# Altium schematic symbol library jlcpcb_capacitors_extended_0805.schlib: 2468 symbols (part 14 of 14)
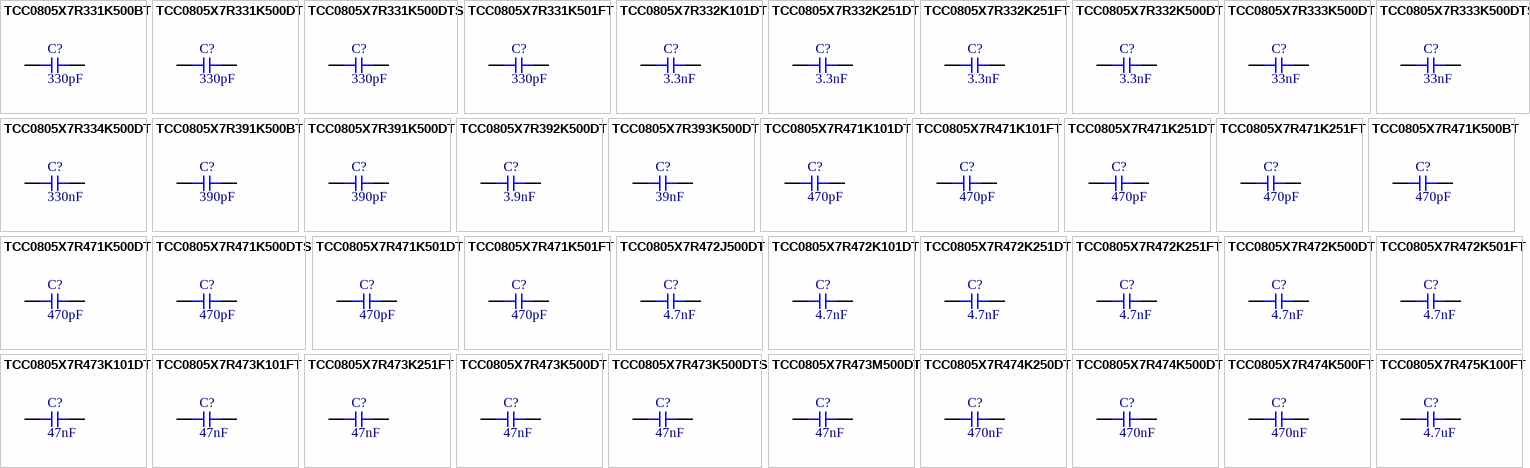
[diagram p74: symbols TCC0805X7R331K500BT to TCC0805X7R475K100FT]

## TCC0805X7R471K251FT
designator C?  Capacitance: 470pF  (hidden comment: *)
Capacitor, Ceramic (MLCC), 470pF, ±10%, 250V, X7R, ±10%, SMD 0805; Manufacturer: CCTC; Manufacturer Part Number: TCC0805X7R471K251FT
footprint CAP-0805 (0805 (2012M) Capacitor)
pins: 1, 2

## TCC0805X7R471K500BT
designator C?  Capacitance: 470pF  (hidden comment: *)
Capacitor, Ceramic (MLCC), 470pF, ±10%, 50V, X7R, ±10%, SMD 0805; Manufacturer: CCTC; Manufacturer Part Number: TCC0805X7R471K500BT
footprint CAP-0805 (0805 (2012M) Capacitor)
pins: 1, 2

## TCC0805X7R471K500DT
designator C?  Capacitance: 470pF  (hidden comment: *)
Capacitor, Ceramic (MLCC), 470pF, ±10%, 50V, X7R, ±10%, SMD 0805; Manufacturer: CCTC; Manufacturer Part Number: TCC0805X7R471K500DT
footprint CAP-0805 (0805 (2012M) Capacitor)
pins: 1, 2

## TCC0805X7R471K500DTS
designator C?  Capacitance: 470pF  (hidden comment: *)
Capacitor, Ceramic (MLCC), 470pF, ±10%, 50V, X7R, ±10%, SMD 0805; Manufacturer: CCTC; Manufacturer Part Number: TCC0805X7R471K500DTS
footprint CAP-0805 (0805 (2012M) Capacitor)
pins: 1, 2

## TCC0805X7R471K501DT
designator C?  Capacitance: 470pF  (hidden comment: *)
Capacitor, Ceramic (MLCC), 470pF, ±10%, 500V, X7R, ±10%, SMD 0805; Manufacturer: CCTC; Manufacturer Part Number: TCC0805X7R471K501DT
footprint CAP-0805 (0805 (2012M) Capacitor)
pins: 1, 2

## TCC0805X7R471K501FT
designator C?  Capacitance: 470pF  (hidden comment: *)
Capacitor, Ceramic (MLCC), 470pF, ±10%, 500V, X7R, ±10%, SMD 0805; Manufacturer: CCTC; Manufacturer Part Number: TCC0805X7R471K501FT
footprint CAP-0805 (0805 (2012M) Capacitor)
pins: 1, 2

## TCC0805X7R472J500DT
designator C?  Capacitance: 4.7nF  (hidden comment: *)
Capacitor, Ceramic (MLCC), 4.7nF, ±5%, 50V, X7R, ±5%, SMD 0805; Manufacturer: CCTC; Manufacturer Part Number: TCC0805X7R472J500DT
footprint CAP-0805 (0805 (2012M) Capacitor)
pins: 1, 2

## TCC0805X7R472K101DT
designator C?  Capacitance: 4.7nF  (hidden comment: *)
Capacitor, Ceramic (MLCC), 4.7nF, ±10%, 100V, X7R, ±10%, SMD 0805; Manufacturer: CCTC; Manufacturer Part Number: TCC0805X7R472K101DT
footprint CAP-0805 (0805 (2012M) Capacitor)
pins: 1, 2

## TCC0805X7R472K251DT
designator C?  Capacitance: 4.7nF  (hidden comment: *)
Capacitor, Ceramic (MLCC), 4.7nF, ±10%, 250V, X7R, ±10%, SMD 0805; Manufacturer: CCTC; Manufacturer Part Number: TCC0805X7R472K251DT
footprint CAP-0805 (0805 (2012M) Capacitor)
pins: 1, 2

## TCC0805X7R472K251FT
designator C?  Capacitance: 4.7nF  (hidden comment: *)
Capacitor, Ceramic (MLCC), 4.7nF, ±10%, 250V, X7R, ±10%, SMD 0805; Manufacturer: CCTC; Manufacturer Part Number: TCC0805X7R472K251FT
footprint CAP-0805 (0805 (2012M) Capacitor)
pins: 1, 2

## TCC0805X7R472K500DT
designator C?  Capacitance: 4.7nF  (hidden comment: *)
Capacitor, Ceramic (MLCC), 4.7nF, ±10%, 50V, X7R, ±10%, SMD 0805; Manufacturer: CCTC; Manufacturer Part Number: TCC0805X7R472K500DT
footprint CAP-0805 (0805 (2012M) Capacitor)
pins: 1, 2

## TCC0805X7R472K501FT
designator C?  Capacitance: 4.7nF  (hidden comment: *)
Capacitor, Ceramic (MLCC), 4.7nF, ±10%, 500V, X7R, ±10%, SMD 0805; Manufacturer: CCTC; Manufacturer Part Number: TCC0805X7R472K501FT
footprint CAP-0805 (0805 (2012M) Capacitor)
pins: 1, 2

## TCC0805X7R473K101DT
designator C?  Capacitance: 47nF  (hidden comment: *)
Capacitor, Ceramic (MLCC), 47nF, ±10%, 100V, X7R, ±10%, SMD 0805; Manufacturer: CCTC; Manufacturer Part Number: TCC0805X7R473K101DT
footprint CAP-0805 (0805 (2012M) Capacitor)
pins: 1, 2

## TCC0805X7R473K101FT
designator C?  Capacitance: 47nF  (hidden comment: *)
Capacitor, Ceramic (MLCC), 47nF, ±10%, 100V, X7R, ±10%, SMD 0805; Manufacturer: CCTC; Manufacturer Part Number: TCC0805X7R473K101FT
footprint CAP-0805 (0805 (2012M) Capacitor)
pins: 1, 2

## TCC0805X7R473K251FT
designator C?  Capacitance: 47nF  (hidden comment: *)
Capacitor, Ceramic (MLCC), 47nF, ±10%, 250V, X7R, ±10%, SMD 0805; Manufacturer: CCTC; Manufacturer Part Number: TCC0805X7R473K251FT
footprint CAP-0805 (0805 (2012M) Capacitor)
pins: 1, 2

## TCC0805X7R473K500DT
designator C?  Capacitance: 47nF  (hidden comment: *)
Capacitor, Ceramic (MLCC), 47nF, ±10%, 50V, X7R, ±10%, SMD 0805; Manufacturer: CCTC; Manufacturer Part Number: TCC0805X7R473K500DT
footprint CAP-0805 (0805 (2012M) Capacitor)
pins: 1, 2

## TCC0805X7R473K500DTS
designator C?  Capacitance: 47nF  (hidden comment: *)
Capacitor, Ceramic (MLCC), 47nF, ±10%, 50V, X7R, ±10%, SMD 0805; Manufacturer: CCTC; Manufacturer Part Number: TCC0805X7R473K500DTS
footprint CAP-0805 (0805 (2012M) Capacitor)
pins: 1, 2

## TCC0805X7R473M500DT
designator C?  Capacitance: 47nF  (hidden comment: *)
Capacitor, Ceramic (MLCC), 47nF, ±20%, 50V, X7R, ±20%, SMD 0805; Manufacturer: CCTC; Manufacturer Part Number: TCC0805X7R473M500DT
footprint CAP-0805 (0805 (2012M) Capacitor)
pins: 1, 2

## TCC0805X7R474K250DT
designator C?  Capacitance: 470nF  (hidden comment: *)
Capacitor, Ceramic (MLCC), 470nF, ±10%, 25V, X7R, ±10%, SMD 0805; Manufacturer: CCTC; Manufacturer Part Number: TCC0805X7R474K250DT
footprint CAP-0805 (0805 (2012M) Capacitor)
pins: 1, 2

## TCC0805X7R474K500DT
designator C?  Capacitance: 470nF  (hidden comment: *)
Capacitor, Ceramic (MLCC), 470nF, ±10%, 50V, X7R, ±10%, SMD 0805; Manufacturer: CCTC; Manufacturer Part Number: TCC0805X7R474K500DT
footprint CAP-0805 (0805 (2012M) Capacitor)
pins: 1, 2

## TCC0805X7R474K500FT
designator C?  Capacitance: 470nF  (hidden comment: *)
Capacitor, Ceramic (MLCC), 470nF, ±10%, 50V, X7R, ±10%, SMD 0805; Manufacturer: CCTC; Manufacturer Part Number: TCC0805X7R474K500FT
footprint CAP-0805 (0805 (2012M) Capacitor)
pins: 1, 2

## TCC0805X7R475K100FT
designator C?  Capacitance: 4.7uF  (hidden comment: *)
Capacitor, Ceramic (MLCC), 4.7uF, ±10%, 10V, X7R, ±10%, SMD 0805; Manufacturer: CCTC; Manufacturer Part Number: TCC0805X7R475K100FT
footprint CAP-0805 (0805 (2012M) Capacitor)
pins: 1, 2

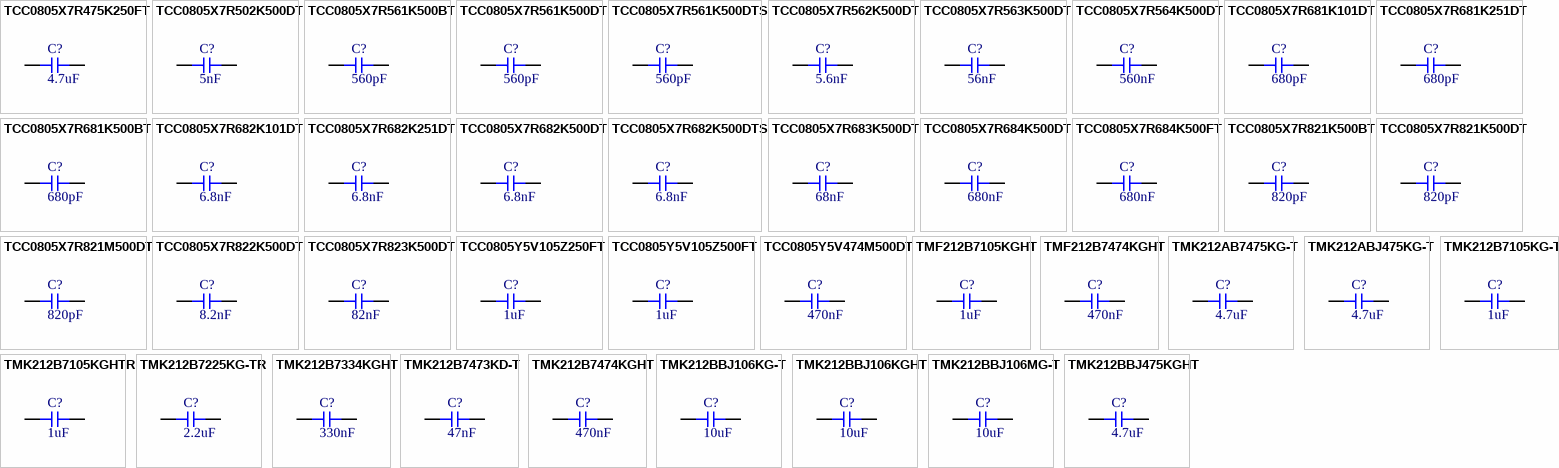
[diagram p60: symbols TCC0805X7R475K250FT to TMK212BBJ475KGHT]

## TCC0805X7R475K250FT
designator C?  Capacitance: 4.7uF  (hidden comment: *)
Capacitor, Ceramic (MLCC), 4.7uF, ±10%, 25V, X7R, ±10%, SMD 0805; Manufacturer: CCTC; Manufacturer Part Number: TCC0805X7R475K250FT
footprint CAP-0805 (0805 (2012M) Capacitor)
pins: 1, 2

## TCC0805X7R502K500DT
designator C?  Capacitance: 5nF  (hidden comment: *)
Capacitor, Ceramic (MLCC), 5nF, ±10%, 50V, X7R, ±10%, SMD 0805; Manufacturer: CCTC; Manufacturer Part Number: TCC0805X7R502K500DT
footprint CAP-0805 (0805 (2012M) Capacitor)
pins: 1, 2

## TCC0805X7R561K500BT
designator C?  Capacitance: 560pF  (hidden comment: *)
Capacitor, Ceramic (MLCC), 560pF, ±10%, 50V, X7R, ±10%, SMD 0805; Manufacturer: CCTC; Manufacturer Part Number: TCC0805X7R561K500BT
footprint CAP-0805 (0805 (2012M) Capacitor)
pins: 1, 2

## TCC0805X7R561K500DT
designator C?  Capacitance: 560pF  (hidden comment: *)
Capacitor, Ceramic (MLCC), 560pF, ±10%, 50V, X7R, ±10%, SMD 0805; Manufacturer: CCTC; Manufacturer Part Number: TCC0805X7R561K500DT
footprint CAP-0805 (0805 (2012M) Capacitor)
pins: 1, 2

## TCC0805X7R561K500DTS
designator C?  Capacitance: 560pF  (hidden comment: *)
Capacitor, Ceramic (MLCC), 560pF, ±10%, 50V, X7R, ±10%, SMD 0805; Manufacturer: CCTC; Manufacturer Part Number: TCC0805X7R561K500DTS
footprint CAP-0805 (0805 (2012M) Capacitor)
pins: 1, 2

## TCC0805X7R562K500DT
designator C?  Capacitance: 5.6nF  (hidden comment: *)
Capacitor, Ceramic (MLCC), 5.6nF, ±10%, 50V, X7R, ±10%, SMD 0805; Manufacturer: CCTC; Manufacturer Part Number: TCC0805X7R562K500DT
footprint CAP-0805 (0805 (2012M) Capacitor)
pins: 1, 2

## TCC0805X7R563K500DT
designator C?  Capacitance: 56nF  (hidden comment: *)
Capacitor, Ceramic (MLCC), 56nF, ±10%, 50V, X7R, ±10%, SMD 0805; Manufacturer: CCTC; Manufacturer Part Number: TCC0805X7R563K500DT
footprint CAP-0805 (0805 (2012M) Capacitor)
pins: 1, 2

## TCC0805X7R564K500DT
designator C?  Capacitance: 560nF  (hidden comment: *)
Capacitor, Ceramic (MLCC), 560nF, ±10%, 50V, X7R, ±10%, SMD 0805; Manufacturer: CCTC; Manufacturer Part Number: TCC0805X7R564K500DT
footprint CAP-0805 (0805 (2012M) Capacitor)
pins: 1, 2

## TCC0805X7R681K101DT
designator C?  Capacitance: 680pF  (hidden comment: *)
Capacitor, Ceramic (MLCC), 680pF, ±10%, 100V, X7R, ±10%, SMD 0805; Manufacturer: CCTC; Manufacturer Part Number: TCC0805X7R681K101DT
footprint CAP-0805 (0805 (2012M) Capacitor)
pins: 1, 2

## TCC0805X7R681K251DT
designator C?  Capacitance: 680pF  (hidden comment: *)
Capacitor, Ceramic (MLCC), 680pF, ±10%, 250V, X7R, ±10%, SMD 0805; Manufacturer: CCTC; Manufacturer Part Number: TCC0805X7R681K251DT
footprint CAP-0805 (0805 (2012M) Capacitor)
pins: 1, 2

## TCC0805X7R681K500BT
designator C?  Capacitance: 680pF  (hidden comment: *)
Capacitor, Ceramic (MLCC), 680pF, ±10%, 50V, X7R, ±10%, SMD 0805; Manufacturer: CCTC; Manufacturer Part Number: TCC0805X7R681K500BT
footprint CAP-0805 (0805 (2012M) Capacitor)
pins: 1, 2

## TCC0805X7R682K101DT
designator C?  Capacitance: 6.8nF  (hidden comment: *)
Capacitor, Ceramic (MLCC), 6.8nF, ±10%, 100V, X7R, ±10%, SMD 0805; Manufacturer: CCTC; Manufacturer Part Number: TCC0805X7R682K101DT
footprint CAP-0805 (0805 (2012M) Capacitor)
pins: 1, 2

## TCC0805X7R682K251DT
designator C?  Capacitance: 6.8nF  (hidden comment: *)
Capacitor, Ceramic (MLCC), 6.8nF, ±10%, 250V, X7R, ±10%, SMD 0805; Manufacturer: CCTC; Manufacturer Part Number: TCC0805X7R682K251DT
footprint CAP-0805 (0805 (2012M) Capacitor)
pins: 1, 2

## TCC0805X7R682K500DT
designator C?  Capacitance: 6.8nF  (hidden comment: *)
Capacitor, Ceramic (MLCC), 6.8nF, ±10%, 50V, X7R, ±10%, SMD 0805; Manufacturer: CCTC; Manufacturer Part Number: TCC0805X7R682K500DT
footprint CAP-0805 (0805 (2012M) Capacitor)
pins: 1, 2

## TCC0805X7R682K500DTS
designator C?  Capacitance: 6.8nF  (hidden comment: *)
Capacitor, Ceramic (MLCC), 6.8nF, ±10%, 50V, X7R, ±10%, SMD 0805; Manufacturer: CCTC; Manufacturer Part Number: TCC0805X7R682K500DTS
footprint CAP-0805 (0805 (2012M) Capacitor)
pins: 1, 2

## TCC0805X7R683K500DT
designator C?  Capacitance: 68nF  (hidden comment: *)
Capacitor, Ceramic (MLCC), 68nF, ±10%, 50V, X7R, ±10%, SMD 0805; Manufacturer: CCTC; Manufacturer Part Number: TCC0805X7R683K500DT
footprint CAP-0805 (0805 (2012M) Capacitor)
pins: 1, 2

## TCC0805X7R684K500DT
designator C?  Capacitance: 680nF  (hidden comment: *)
Capacitor, Ceramic (MLCC), 680nF, ±10%, 50V, X7R, ±10%, SMD 0805; Manufacturer: CCTC; Manufacturer Part Number: TCC0805X7R684K500DT
footprint CAP-0805 (0805 (2012M) Capacitor)
pins: 1, 2

## TCC0805X7R684K500FT
designator C?  Capacitance: 680nF  (hidden comment: *)
Capacitor, Ceramic (MLCC), 680nF, ±10%, 50V, X7R, ±10%, SMD 0805; Manufacturer: CCTC; Manufacturer Part Number: TCC0805X7R684K500FT
footprint CAP-0805 (0805 (2012M) Capacitor)
pins: 1, 2

## TCC0805X7R821K500BT
designator C?  Capacitance: 820pF  (hidden comment: *)
Capacitor, Ceramic (MLCC), 820pF, ±10%, 50V, X7R, ±10%, SMD 0805; Manufacturer: CCTC; Manufacturer Part Number: TCC0805X7R821K500BT
footprint CAP-0805 (0805 (2012M) Capacitor)
pins: 1, 2

## TCC0805X7R821K500DT
designator C?  Capacitance: 820pF  (hidden comment: *)
Capacitor, Ceramic (MLCC), 820pF, ±10%, 50V, X7R, ±10%, SMD 0805; Manufacturer: CCTC; Manufacturer Part Number: TCC0805X7R821K500DT
footprint CAP-0805 (0805 (2012M) Capacitor)
pins: 1, 2

## TCC0805X7R821M500DT
designator C?  Capacitance: 820pF  (hidden comment: *)
Capacitor, Ceramic (MLCC), 820pF, ±20%, 50V, X7R, ±20%, SMD 0805; Manufacturer: CCTC; Manufacturer Part Number: TCC0805X7R821M500DT
footprint CAP-0805 (0805 (2012M) Capacitor)
pins: 1, 2

## TCC0805X7R822K500DT
designator C?  Capacitance: 8.2nF  (hidden comment: *)
Capacitor, Ceramic (MLCC), 8.2nF, ±10%, 50V, X7R, ±10%, SMD 0805; Manufacturer: CCTC; Manufacturer Part Number: TCC0805X7R822K500DT
footprint CAP-0805 (0805 (2012M) Capacitor)
pins: 1, 2

## TCC0805X7R823K500DT
designator C?  Capacitance: 82nF  (hidden comment: *)
Capacitor, Ceramic (MLCC), 82nF, ±10%, 50V, X7R, ±10%, SMD 0805; Manufacturer: CCTC; Manufacturer Part Number: TCC0805X7R823K500DT
footprint CAP-0805 (0805 (2012M) Capacitor)
pins: 1, 2

## TCC0805Y5V105Z250FT
designator C?  Capacitance: 1uF  (hidden comment: *)
Capacitor, Ceramic (MLCC), 1uF, 25V, Y5V, SMD 0805; Manufacturer: CCTC; Manufacturer Part Number: TCC0805Y5V105Z250FT; Temperature Rating: -20%~+80%
footprint CAP-0805 (0805 (2012M) Capacitor)
pins: 1, 2

## TCC0805Y5V105Z500FT
designator C?  Capacitance: 1uF  (hidden comment: *)
Capacitor, Ceramic (MLCC), 1uF, 50V, Y5V, SMD 0805; Manufacturer: CCTC; Manufacturer Part Number: TCC0805Y5V105Z500FT; Temperature Rating: -20%~+80%
footprint CAP-0805 (0805 (2012M) Capacitor)
pins: 1, 2

## TCC0805Y5V474M500DT
designator C?  Capacitance: 470nF  (hidden comment: *)
Capacitor, Ceramic (MLCC), 470nF, ±20%, 50V, Y5V, ±20%, SMD 0805; Manufacturer: CCTC; Manufacturer Part Number: TCC0805Y5V474M500DT
footprint CAP-0805 (0805 (2012M) Capacitor)
pins: 1, 2

## TMF212B7105KGHT
designator C?  Capacitance: 1uF  (hidden comment: *)
Capacitor, Ceramic (MLCC), 1uF, ±10%, 25V, X7R, ±10%, SMD 0805; Manufacturer: Taiyo Yuden; Manufacturer Part Number: TMF212B7105KGHT
footprint CAP-0805 (0805 (2012M) Capacitor)
pins: 1, 2

## TMF212B7474KGHT
designator C?  Capacitance: 470nF  (hidden comment: *)
Capacitor, Ceramic (MLCC), 470nF, ±10%, 25V, X7R, ±10%, SMD 0805; Manufacturer: Taiyo Yuden; Manufacturer Part Number: TMF212B7474KGHT
footprint CAP-0805 (0805 (2012M) Capacitor)
pins: 1, 2

## TMK212AB7475KG-T
designator C?  Capacitance: 4.7uF  (hidden comment: *)
Capacitor, Ceramic (MLCC), 4.7uF, ±10%, 25V, X7R, ±10%, SMD 0805; Manufacturer: Taiyo Yuden; Manufacturer Part Number: TMK212AB7475KG-T
footprint CAP-0805 (0805 (2012M) Capacitor)
pins: 1, 2

## TMK212ABJ475KG-T
designator C?  Capacitance: 4.7uF  (hidden comment: *)
Capacitor, Ceramic (MLCC), 4.7uF, ±10%, 25V, X5R, ±10%, SMD 0805; Manufacturer: Taiyo Yuden; Manufacturer Part Number: TMK212ABJ475KG-T
footprint CAP-0805 (0805 (2012M) Capacitor)
pins: 1, 2

## TMK212B7105KG-T
designator C?  Capacitance: 1uF  (hidden comment: *)
Capacitor, Ceramic (MLCC), 1uF, ±10%, 25V, X7R, ±10%, SMD 0805; Manufacturer: Taiyo Yuden; Manufacturer Part Number: TMK212B7105KG-T
footprint CAP-0805 (0805 (2012M) Capacitor)
pins: 1, 2

## TMK212B7105KGHTR
designator C?  Capacitance: 1uF  (hidden comment: *)
Capacitor, Ceramic (MLCC), 1uF, ±10%, 25V, X7R, ±10%, SMD 0805; Manufacturer: Taiyo Yuden; Manufacturer Part Number: TMK212B7105KGHTR
footprint CAP-0805 (0805 (2012M) Capacitor)
pins: 1, 2

## TMK212B7225KG-TR
designator C?  Capacitance: 2.2uF  (hidden comment: *)
Capacitor, Ceramic (MLCC), 2.2uF, ±10%, 25V, X7R, ±10%, SMD 0805; Manufacturer: Taiyo Yuden; Manufacturer Part Number: TMK212B7225KG-TR
footprint CAP-0805 (0805 (2012M) Capacitor)
pins: 1, 2

## TMK212B7334KGHT
designator C?  Capacitance: 330nF  (hidden comment: *)
Capacitor, Ceramic (MLCC), 330nF, ±10%, 25V, X7R, ±10%, SMD 0805; Manufacturer: Taiyo Yuden; Manufacturer Part Number: TMK212B7334KGHT
footprint CAP-0805 (0805 (2012M) Capacitor)
pins: 1, 2

## TMK212B7473KD-T
designator C?  Capacitance: 47nF  (hidden comment: *)
Capacitor, Ceramic (MLCC), 47nF, ±10%, 25V, X7R, ±10%, SMD 0805; Manufacturer: Taiyo Yuden; Manufacturer Part Number: TMK212B7473KD-T
footprint CAP-0805 (0805 (2012M) Capacitor)
pins: 1, 2

## TMK212B7474KGHT
designator C?  Capacitance: 470nF  (hidden comment: *)
Capacitor, Ceramic (MLCC), 470nF, ±10%, 25V, X7R, ±10%, SMD 0805; Manufacturer: Taiyo Yuden; Manufacturer Part Number: TMK212B7474KGHT
footprint CAP-0805 (0805 (2012M) Capacitor)
pins: 1, 2

## TMK212BBJ106KG-T
designator C?  Capacitance: 10uF  (hidden comment: *)
Capacitor, Ceramic (MLCC), 10uF, ±10%, 25V, X5R, ±10%, SMD 0805; Manufacturer: Taiyo Yuden; Manufacturer Part Number: TMK212BBJ106KG-T
footprint CAP-0805 (0805 (2012M) Capacitor)
pins: 1, 2

## TMK212BBJ106KGHT
designator C?  Capacitance: 10uF  (hidden comment: *)
Capacitor, Ceramic (MLCC), 10uF, ±10%, 25V, X5R, ±10%, SMD 0805; Manufacturer: Taiyo Yuden; Manufacturer Part Number: TMK212BBJ106KGHT
footprint CAP-0805 (0805 (2012M) Capacitor)
pins: 1, 2

## TMK212BBJ106MG-T
designator C?  Capacitance: 10uF  (hidden comment: *)
Capacitor, Ceramic (MLCC), 10uF, ±20%, 25V, X5R, ±20%, SMD 0805; Manufacturer: Taiyo Yuden; Manufacturer Part Number: TMK212BBJ106MG-T
footprint CAP-0805 (0805 (2012M) Capacitor)
pins: 1, 2

## TMK212BBJ475KGHT
designator C?  Capacitance: 4.7uF  (hidden comment: *)
Capacitor, Ceramic (MLCC), 4.7uF, ±10%, 25V, X5R, ±10%, SMD 0805; Manufacturer: Taiyo Yuden; Manufacturer Part Number: TMK212BBJ475KGHT
footprint CAP-0805 (0805 (2012M) Capacitor)
pins: 1, 2

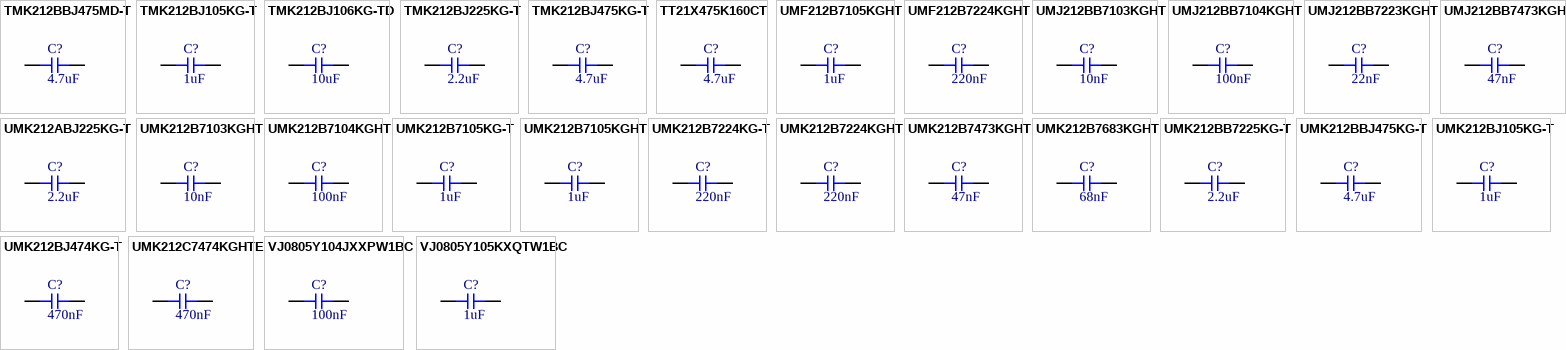
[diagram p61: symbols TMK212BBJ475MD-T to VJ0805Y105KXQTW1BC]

## TMK212BBJ475MD-T
designator C?  Capacitance: 4.7uF  (hidden comment: *)
Capacitor, Ceramic (MLCC), 4.7uF, ±20%, 25V, X5R, ±20%, SMD 0805; Manufacturer: Taiyo Yuden; Manufacturer Part Number: TMK212BBJ475MD-T
footprint CAP-0805 (0805 (2012M) Capacitor)
pins: 1, 2

## TMK212BJ105KG-T
designator C?  Capacitance: 1uF  (hidden comment: *)
Capacitor, Ceramic (MLCC), 1uF, ±10%, 25V, X5R, ±10%, SMD 0805; Manufacturer: Taiyo Yuden; Manufacturer Part Number: TMK212BJ105KG-T
footprint CAP-0805 (0805 (2012M) Capacitor)
pins: 1, 2

## TMK212BJ106KG-TD
designator C?  Capacitance: 10uF  (hidden comment: *)
Capacitor, Ceramic (MLCC), 10uF, ±10%, 25V, ±10%, SMD 0805; Manufacturer: Taiyo Yuden; Manufacturer Part Number: TMK212BJ106KG-TD
footprint CAP-0805 (0805 (2012M) Capacitor)
pins: 1, 2

## TMK212BJ225KG-T
designator C?  Capacitance: 2.2uF  (hidden comment: *)
Capacitor, Ceramic (MLCC), 2.2uF, ±10%, 25V, X5R, ±10%, SMD 0805; Manufacturer: Taiyo Yuden; Manufacturer Part Number: TMK212BJ225KG-T
footprint CAP-0805 (0805 (2012M) Capacitor)
pins: 1, 2

## TMK212BJ475KG-T
designator C?  Capacitance: 4.7uF  (hidden comment: *)
Capacitor, Ceramic (MLCC), 4.7uF, ±10%, 25V, X5R, ±10%, SMD 0805; Manufacturer: Taiyo Yuden; Manufacturer Part Number: TMK212BJ475KG-T
footprint CAP-0805 (0805 (2012M) Capacitor)
pins: 1, 2

## TT21X475K160CT
designator C?  Capacitance: 4.7uF  (hidden comment: *)
Capacitor, Ceramic (MLCC), 4.7uF, ±10%, 16V, X5R, ±10%, SMD 0805; Manufacturer: Walsin Tech Corp; Manufacturer Part Number: TT21X475K160CT
footprint CAP-0805 (0805 (2012M) Capacitor)
pins: 1, 2

## UMF212B7105KGHT
designator C?  Capacitance: 1uF  (hidden comment: *)
Capacitor, Ceramic (MLCC), 1uF, ±10%, 50V, ±10%, SMD 0805; Manufacturer: Taiyo Yuden; Manufacturer Part Number: UMF212B7105KGHT
footprint CAP-0805 (0805 (2012M) Capacitor)
pins: 1, 2

## UMF212B7224KGHT
designator C?  Capacitance: 220nF  (hidden comment: *)
Capacitor, Ceramic (MLCC), 220nF, ±10%, 50V, X7R, ±10%, SMD 0805; Manufacturer: Taiyo Yuden; Manufacturer Part Number: UMF212B7224KGHT
footprint CAP-0805 (0805 (2012M) Capacitor)
pins: 1, 2

## UMJ212BB7103KGHT
designator C?  Capacitance: 10nF  (hidden comment: *)
Capacitor, Ceramic (MLCC), 10nF, ±10%, 50V, X7R, ±10%, SMD 0805; Manufacturer: Taiyo Yuden; Manufacturer Part Number: UMJ212BB7103KGHT
footprint CAP-0805 (0805 (2012M) Capacitor)
pins: 1, 2

## UMJ212BB7104KGHT
designator C?  Capacitance: 100nF  (hidden comment: *)
Capacitor, Ceramic (MLCC), 100nF, ±10%, 50V, X7R, ±10%, SMD 0805; Manufacturer: Taiyo Yuden; Manufacturer Part Number: UMJ212BB7104KGHT
footprint CAP-0805 (0805 (2012M) Capacitor)
pins: 1, 2

## UMJ212BB7223KGHT
designator C?  Capacitance: 22nF  (hidden comment: *)
Capacitor, Ceramic (MLCC), 22nF, ±10%, 50V, X7R, ±10%, SMD 0805; Manufacturer: Taiyo Yuden; Manufacturer Part Number: UMJ212BB7223KGHT
footprint CAP-0805 (0805 (2012M) Capacitor)
pins: 1, 2

## UMJ212BB7473KGHT
designator C?  Capacitance: 47nF  (hidden comment: *)
Capacitor, Ceramic (MLCC), 47nF, ±10%, 50V, X7R, ±10%, SMD 0805; Manufacturer: Taiyo Yuden; Manufacturer Part Number: UMJ212BB7473KGHT
footprint CAP-0805 (0805 (2012M) Capacitor)
pins: 1, 2

## UMK212ABJ225KG-T
designator C?  Capacitance: 2.2uF  (hidden comment: *)
Capacitor, Ceramic (MLCC), 2.2uF, ±10%, 50V, X5R, ±10%, SMD 0805; Manufacturer: Taiyo Yuden; Manufacturer Part Number: UMK212ABJ225KG-T
footprint CAP-0805 (0805 (2012M) Capacitor)
pins: 1, 2

## UMK212B7103KGHT
designator C?  Capacitance: 10nF  (hidden comment: *)
Capacitor, Ceramic (MLCC), 10nF, ±10%, 50V, X7R, ±10%, SMD 0805; Manufacturer: Taiyo Yuden; Manufacturer Part Number: UMK212B7103KGHT
footprint CAP-0805 (0805 (2012M) Capacitor)
pins: 1, 2

## UMK212B7104KGHT
designator C?  Capacitance: 100nF  (hidden comment: *)
Capacitor, Ceramic (MLCC), 100nF, ±10%, 50V, X7R, ±10%, SMD 0805; Manufacturer: Taiyo Yuden; Manufacturer Part Number: UMK212B7104KGHT
footprint CAP-0805 (0805 (2012M) Capacitor)
pins: 1, 2

## UMK212B7105KG-T
designator C?  Capacitance: 1uF  (hidden comment: *)
Capacitor, Ceramic (MLCC), 1uF, ±10%, 50V, X7R, ±10%, SMD 0805; Manufacturer: Taiyo Yuden; Manufacturer Part Number: UMK212B7105KG-T
footprint CAP-0805 (0805 (2012M) Capacitor)
pins: 1, 2

## UMK212B7105KGHT
designator C?  Capacitance: 1uF  (hidden comment: *)
Capacitor, Ceramic (MLCC), 1uF, ±10%, 50V, ±10%, SMD 0805; Manufacturer: Taiyo Yuden; Manufacturer Part Number: UMK212B7105KGHT
footprint CAP-0805 (0805 (2012M) Capacitor)
pins: 1, 2

## UMK212B7224KG-T
designator C?  Capacitance: 220nF  (hidden comment: *)
Capacitor, Ceramic (MLCC), 220nF, ±10%, 50V, X7R, ±10%, SMD 0805; Manufacturer: Taiyo Yuden; Manufacturer Part Number: UMK212B7224KG-T
footprint CAP-0805 (0805 (2012M) Capacitor)
pins: 1, 2

## UMK212B7224KGHT
designator C?  Capacitance: 220nF  (hidden comment: *)
Capacitor, Ceramic (MLCC), 220nF, ±10%, 50V, X7R, ±10%, SMD 0805; Manufacturer: Taiyo Yuden; Manufacturer Part Number: UMK212B7224KGHT
footprint CAP-0805 (0805 (2012M) Capacitor)
pins: 1, 2

## UMK212B7473KGHT
designator C?  Capacitance: 47nF  (hidden comment: *)
Capacitor, Ceramic (MLCC), 47nF, ±10%, 50V, X7R, ±10%, SMD 0805; Manufacturer: Taiyo Yuden; Manufacturer Part Number: UMK212B7473KGHT
footprint CAP-0805 (0805 (2012M) Capacitor)
pins: 1, 2

## UMK212B7683KGHT
designator C?  Capacitance: 68nF  (hidden comment: *)
Capacitor, Ceramic (MLCC), 68nF, ±10%, 50V, X7R, ±10%, SMD 0805; Manufacturer: Taiyo Yuden; Manufacturer Part Number: UMK212B7683KGHT
footprint CAP-0805 (0805 (2012M) Capacitor)
pins: 1, 2

## UMK212BB7225KG-T
designator C?  Capacitance: 2.2uF  (hidden comment: *)
Capacitor, Ceramic (MLCC), 2.2uF, ±10%, 50V, X7R, ±10%, SMD 0805; Manufacturer: Taiyo Yuden; Manufacturer Part Number: UMK212BB7225KG-T
footprint CAP-0805 (0805 (2012M) Capacitor)
pins: 1, 2

## UMK212BBJ475KG-T
designator C?  Capacitance: 4.7uF  (hidden comment: *)
Capacitor, Ceramic (MLCC), 4.7uF, ±10%, 50V, X5R, ±10%, SMD 0805; Manufacturer: Taiyo Yuden; Manufacturer Part Number: UMK212BBJ475KG-T
footprint CAP-0805 (0805 (2012M) Capacitor)
pins: 1, 2

## UMK212BJ105KG-T
designator C?  Capacitance: 1uF  (hidden comment: *)
Capacitor, Ceramic (MLCC), 1uF, ±10%, 50V, X5R, ±10%, SMD 0805; Manufacturer: Taiyo Yuden; Manufacturer Part Number: UMK212BJ105KG-T
footprint CAP-0805 (0805 (2012M) Capacitor)
pins: 1, 2

## UMK212BJ474KG-T
designator C?  Capacitance: 470nF  (hidden comment: *)
Capacitor, Ceramic (MLCC), 470nF, ±10%, 50V, X5R, ±10%, SMD 0805; Manufacturer: Taiyo Yuden; Manufacturer Part Number: UMK212BJ474KG-T
footprint CAP-0805 (0805 (2012M) Capacitor)
pins: 1, 2

## UMK212C7474KGHTE
designator C?  Capacitance: 470nF  (hidden comment: *)
Capacitor, Ceramic (MLCC), 470nF, ±10%, 50V, X7S, ±10%, SMD 0805; Manufacturer: Taiyo Yuden; Manufacturer Part Number: UMK212C7474KGHTE
footprint CAP-0805 (0805 (2012M) Capacitor)
pins: 1, 2

## VJ0805Y104JXXPW1BC
designator C?  Capacitance: 100nF  (hidden comment: *)
Capacitor, Ceramic (MLCC), 100nF, ±5%, 25V, X7R, ±5%, SMD 0805; Manufacturer: Vishay Intertech; Manufacturer Part Number: VJ0805Y104JXXPW1BC
footprint CAP-0805 (0805 (2012M) Capacitor)
pins: 1, 2

## VJ0805Y105KXQTW1BC
designator C?  Capacitance: 1uF  (hidden comment: *)
Capacitor, Ceramic (MLCC), 1uF, ±10%, 10V, X7R, ±10%, SMD 0805; Manufacturer: Vishay Intertech; Manufacturer Part Number: VJ0805Y105KXQTW1BC
footprint CAP-0805 (0805 (2012M) Capacitor)
pins: 1, 2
